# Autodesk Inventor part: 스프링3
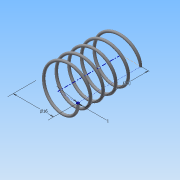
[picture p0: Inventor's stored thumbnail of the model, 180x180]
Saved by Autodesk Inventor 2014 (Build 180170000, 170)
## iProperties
Created: 2015-06
Part Number: 스프링3
Material: 강철, 연강
Document SubType Name: Modeling
Designer: Administrator
Density: 7.86 g/cm^3
Appearance: 강철
Mass: 1.53479 g
Surface Area: 7.89194 cm^2
Volume: 0.195266 cm^3
Author: Administrator
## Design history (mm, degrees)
sketch "스케치1"
  geometry: L1 (0, 0)-(8, 0); L2 (8, 0)-(8, 21.5); L3 (8, 21.5)-(0, 21.5); L4 (0, 21.5)-(0, 0); C1 r 0.5 at (8, 0)
  constraints: 8 end point, 2 parallel, 1 centre point, 1 coincident, 1 horizontal, 1 perpendicular
  dimensions: "d0" = 16 diameter of L2 L4; "d1" = 21.5 distance of L1.end L2.end (derived); "d2" = 1 diameter of C1
feature "코일1" sketch "스케치1" pitch "d3" = 10; turns "d5" = 5; dims "d4" = 21.5 (= d1), "d6" = 0, angle "d7" = 90 deg, angle "d8" = 90 deg, "d9" = 0, "d10" = 0
node "작업 평면1"
sketch "스케치2"
  geometry: L1 (-8.5, 0)-(-7.5, 0) reference; 1 further point
  constraints: 1 horizontal alignment
extrude "돌출1" cut sketch "스케치2" stored distance "d12" = 10; taper "d13" = 0 deg
node "작업 평면2"
sketch "스케치3"
  geometry: L1 (-7.5, 0)-(-8.5, 0) reference; 1 further point
  constraints: 1 horizontal alignment
extrude "돌출2" cut sketch "스케치3" stored distance "d15" = 10; taper "d16" = 0 deg
node "솔리드1"
node "절단 모서리 투영1"
node "절단 모서리 투영2"
other parameters: "d11" = 0, "d14" = 21.5 (= d1)
